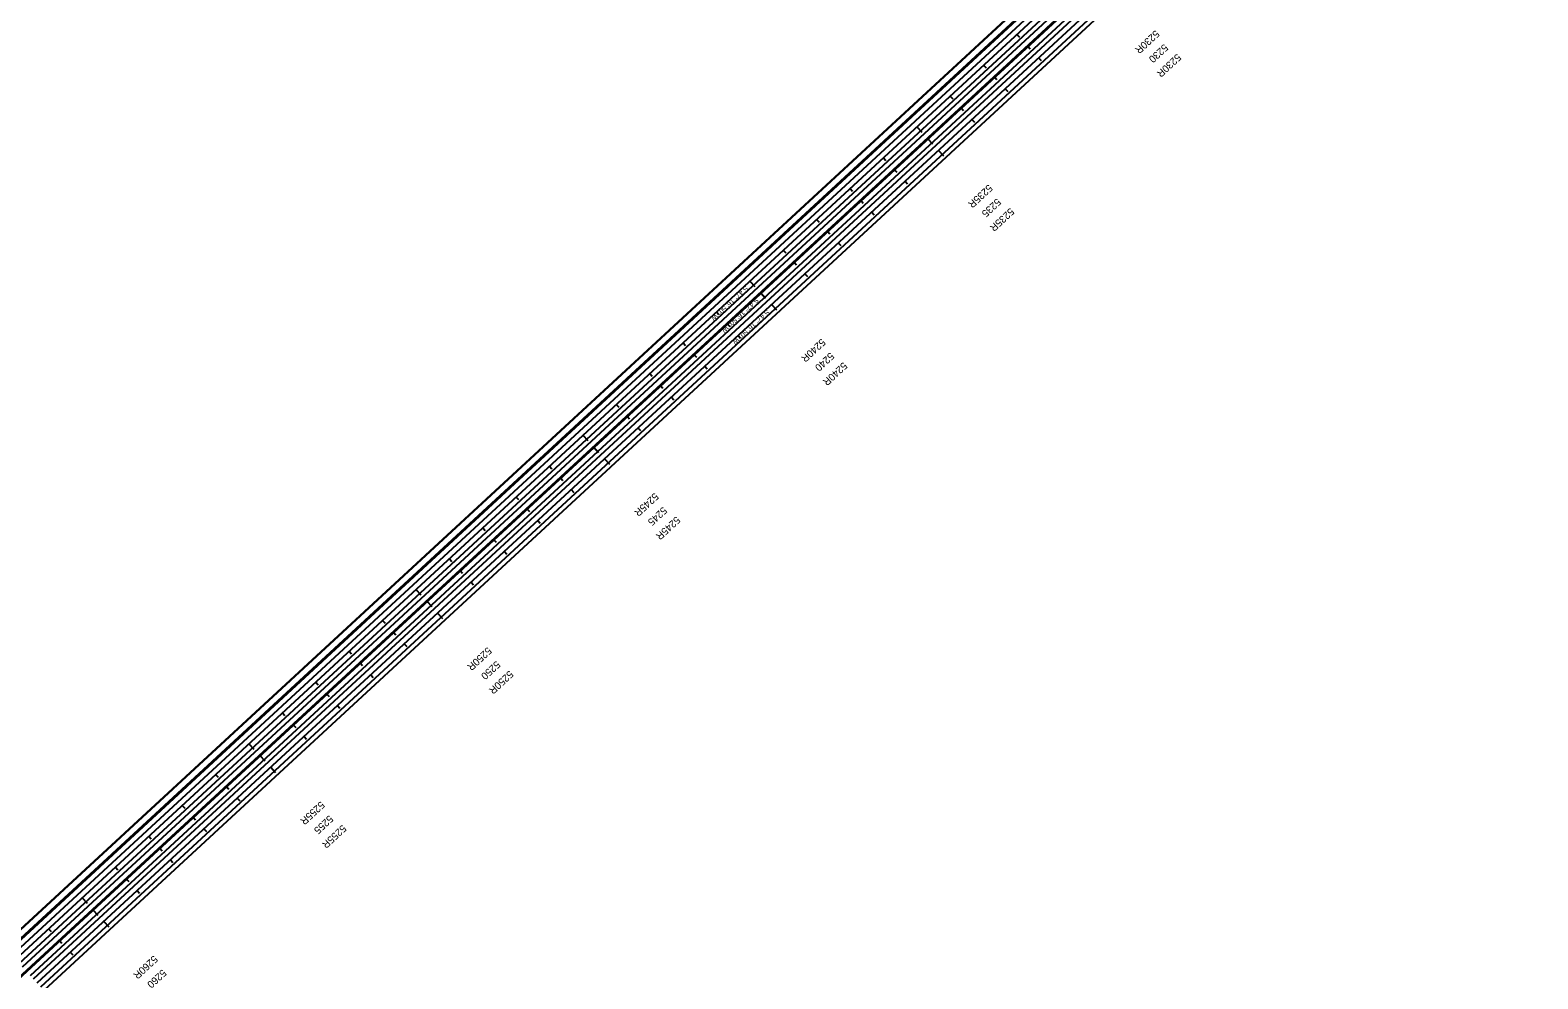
# Model space of a CAD drawing. Extents: x 2160876 to 2175625, y 601634 to 617693.
# Drawn here: x 2165605 to 2168923, y 607589 to 609675 of the extents above; entities that cross this region are included whole.
import ezdxf

# ---------------------------------------------------------------- set-up
doc = ezdxf.new("R2010")
doc.units = 0
for name, color, linetype in [('RD_HC_Cl', 7, 'Continuous'), ('RD_HC_CL_Rel', 7, 'Continuous'), ('RD_HC_Data', 7, 'Continuous'), ('RD_HC_Data_Rel', 7, 'Continuous'), ('RD_HC_Data_Tic', 7, 'Continuous'), ('RD_HC_Data_Tic_Rel', 7, 'Continuous'), ('RD_HC_TX_Rel_Sta50', 7, 'Continuous'), ('RD_HC_TX_Sta50', 7, 'Continuous'), ('RD_PD_Final_LnLine', 7, 'Continuous'), ('RD_PD_Final_TrvlWay', 7, 'Continuous'), ('RD_PD_MedBWall', 7, 'Continuous')]:
    doc.layers.add(name, color=color, linetype=linetype)

msp = doc.modelspace()

# ---------------------------------------------------------------- linework, layer by layer
at = {"layer": 'RD_HC_Cl'}
msp.add_line((2172239.9, 613739.9), (2163704.8, 605858.6), dxfattribs=at)
at = {"layer": 'RD_HC_CL_Rel'}
for p, q in [((2168658.1, 610480.3), (2165572.4, 607631)), ((2168705.8, 610428.6), (2165620.1, 607579.3))]:
    msp.add_line(p, q, dxfattribs=at)
at = {"layer": 'RD_HC_Data_Tic'}
for p, q in [((2167800.3, 609640.4), (2167805.8, 609634.5)), ((2167726.9, 609572.5), (2167732.3, 609566.7)), ((2167653.4, 609504.7), (2167658.8, 609498.8)), ((2167579.9, 609436.9), (2167590.8, 609425.1)), ((2167506.5, 609369), (2167511.9, 609363.1)), ((2167433, 609301.2), (2167438.4, 609295.3)), ((2167359.5, 609233.3), (2167365, 609227.5)), ((2167286.1, 609165.5), (2167291.5, 609159.6)), ((2167212.6, 609097.7), (2167223.4, 609085.9)), ((2167139.1, 609029.8), (2167144.6, 609023.9)), ((2167065.7, 608962), (2167071.1, 608956.1)), ((2166992.2, 608894.1), (2166997.6, 608888.3)), ((2166918.7, 608826.3), (2166924.1, 608820.4)), ((2166845.2, 608758.5), (2166856.1, 608746.7)), ((2166771.8, 608690.6), (2166777.2, 608684.7)), ((2166698.3, 608622.8), (2166703.7, 608616.9)), ((2166624.8, 608554.9), (2166630.3, 608549.1)), ((2166551.4, 608487.1), (2166556.8, 608481.2)), ((2166477.9, 608419.2), (2166488.8, 608407.5)), ((2166404.4, 608351.4), (2166409.9, 608345.5)), ((2166331, 608283.6), (2166336.4, 608277.7)), ((2166257.5, 608215.7), (2166262.9, 608209.8)), ((2166184, 608147.9), (2166189.5, 608142)), ((2166110.6, 608080), (2166121.4, 608068.3)), ((2166037.1, 608012.2), (2166042.5, 608006.3)), ((2165963.6, 607944.4), (2165969.1, 607938.5)), ((2165890.2, 607876.5), (2165895.6, 607870.6)), ((2165816.7, 607808.7), (2165822.1, 607802.8)), ((2165743.2, 607740.8), (2165754.1, 607729.1)), ((2165669.8, 607673), (2165675.2, 607667.1))]:
    msp.add_line(p, q, dxfattribs=at)
at = {"layer": 'RD_HC_Data_Tic_Rel'}
for p, q in [((2167776.5, 609666.3), (2167781.9, 609660.4)), ((2167703, 609598.4), (2167708.5, 609592.5)), ((2167824.2, 609614.6), (2167829.7, 609608.7)), ((2167629.6, 609530.6), (2167635, 609524.7)), ((2167750.8, 609546.7), (2167756.2, 609540.9)), ((2167556.1, 609462.7), (2167567, 609451)), ((2167677.3, 609478.9), (2167682.7, 609473)), ((2167482.6, 609394.9), (2167488.1, 609389)), ((2167603.8, 609411.1), (2167614.7, 609399.3)), ((2167530.4, 609343.2), (2167535.8, 609337.3)), ((2167409.2, 609327), (2167414.6, 609321.2)), ((2167456.9, 609275.4), (2167462.3, 609269.5)), ((2167335.7, 609259.2), (2167341.1, 609253.3)), ((2167383.4, 609207.5), (2167388.8, 609201.7)), ((2167262.2, 609191.4), (2167267.7, 609185.5)), ((2167310, 609139.7), (2167315.4, 609133.8)), ((2167188.8, 609123.5), (2167199.6, 609111.8)), ((2167236.5, 609071.9), (2167247.3, 609060.1)), ((2167115.3, 609055.7), (2167120.7, 609049.8)), ((2167163, 609004), (2167168.4, 608998.1)), ((2167041.8, 608987.8), (2167047.3, 608982)), ((2167089.5, 608936.2), (2167095, 608930.3)), ((2166968.4, 608920), (2166973.8, 608914.1)), ((2167016.1, 608868.3), (2167021.5, 608862.5)), ((2166894.9, 608852.2), (2166900.3, 608846.3)), ((2166942.6, 608800.5), (2166948, 608794.6)), ((2166821.4, 608784.3), (2166832.3, 608772.6)), ((2166869.1, 608732.6), (2166880, 608720.9)), ((2166748, 608716.5), (2166753.4, 608710.6)), ((2166795.7, 608664.8), (2166801.1, 608658.9)), ((2166674.5, 608648.6), (2166679.9, 608642.8)), ((2166601, 608580.8), (2166606.4, 608574.9)), ((2166722.2, 608597), (2166727.6, 608591.1)), ((2166527.6, 608513), (2166533, 608507.1)), ((2166648.7, 608529.1), (2166654.2, 608523.2)), ((2166454.1, 608445.1), (2166464.9, 608433.4)), ((2166575.3, 608461.3), (2166580.7, 608455.4)), ((2166380.6, 608377.3), (2166386, 608371.4)), ((2166501.8, 608393.4), (2166512.7, 608381.7)), ((2166307.1, 608309.4), (2166312.6, 608303.6)), ((2166428.3, 608325.6), (2166433.8, 608319.7)), ((2166233.7, 608241.6), (2166239.1, 608235.7)), ((2166354.9, 608257.8), (2166360.3, 608251.9)), ((2166160.2, 608173.8), (2166165.6, 608167.9)), ((2166281.4, 608189.9), (2166286.8, 608184)), ((2166086.7, 608105.9), (2166097.6, 608094.2)), ((2166207.9, 608122.1), (2166213.4, 608116.2)), ((2166013.3, 608038.1), (2166018.7, 608032.2)), ((2166134.5, 608054.2), (2166145.3, 608042.5)), ((2165939.8, 607970.2), (2165945.2, 607964.4)), ((2166061, 607986.4), (2166066.4, 607980.5)), ((2165866.3, 607902.4), (2165871.8, 607896.5)), ((2165987.5, 607918.6), (2165992.9, 607912.7)), ((2165914.1, 607850.7), (2165919.5, 607844.8)), ((2165792.9, 607834.5), (2165798.3, 607828.7)), ((2165840.6, 607782.9), (2165846, 607777)), ((2165719.4, 607766.7), (2165730.3, 607755)), ((2165767.1, 607715), (2165778, 607703.3)), ((2165645.9, 607698.9), (2165651.4, 607693)), ((2165693.6, 607647.2), (2165699.1, 607641.3))]:
    msp.add_line(p, q, dxfattribs=at)
at = {"layer": 'RD_PD_Final_LnLine'}
for p, q in [((2168630.1, 610510.7), (2165544.4, 607661.4)), ((2168630.7, 610509.9), (2165545.1, 607660.6)), ((2168650, 610489.1), (2165564.3, 607639.8)), ((2168658.1, 610480.3), (2165572.4, 607631)), ((2168666.2, 610471.5), (2165580.6, 607622.2)), ((2168697.7, 610437.5), (2165612, 607588.1)), ((2168705.8, 610428.6), (2165620.1, 607579.3)), ((2168714, 610419.8), (2165628.3, 607570.5))]:
    msp.add_line(p, q, dxfattribs=at)
at = {"layer": 'RD_PD_Final_TrvlWay'}
for p, q in [((2168641.8, 610497.9), (2165556.1, 607648.6)), ((2168673, 610464.1), (2165587.4, 607614.8)), ((2168690.9, 610444.8), (2165605.2, 607595.5)), ((2168720.7, 610412.5), (2165635.1, 607563.2))]:
    msp.add_line(p, q, dxfattribs=at)
at = {"layer": 'RD_PD_MedBWall'}
for p, q in [((2168640.2, 610499.7), (2165554.6, 607650.3)), ((2168641.8, 610497.9), (2165556.1, 607648.6)), ((2168454, 610245.6), (2165100.2, 607148.7)), ((2168455.6, 610243.9), (2165101.8, 607146.9))]:
    msp.add_line(p, q, dxfattribs=at)

# ---------------------------------------------------------------- texts
at = {"layer": 'RD_HC_Data'}
msp.add_text('S 47° 16\' 50" W', height=10.8, rotation=222.7195, dxfattribs=at).set_placement((2167202.1, 609087.8))
at = {"layer": 'RD_HC_Data_Rel'}
for p in [(2167179.3, 609113.6), (2167226.3, 609061.4)]:
    msp.add_text('S 47° 16\' 50" W', height=10.8, rotation=222.7195, dxfattribs=at).set_placement(p)
at = {"layer": 'RD_HC_TX_Rel_Sta50'}
for s, p in [('5230R', (2168081.1, 609676.5)), ('5230R', (2168128.8, 609624.8)), ('5235R', (2167713.8, 609337.3)), ('5235R', (2167761.5, 609285.6)), ('5240R', (2167346.4, 608998.1)), ('5240R', (2167394.2, 608946.4)), ('5245R', (2166979.1, 608658.9)), ('5245R', (2167026.8, 608607.2)), ('5250R', (2166611.8, 608319.7)), ('5250R', (2166659.5, 608268)), ('5255R', (2166244.4, 607980.5)), ('5255R', (2166292.1, 607928.8)), ('5260R', (2165877.1, 607641.3))]:
    msp.add_text(s, height=16, rotation=222.7195, dxfattribs=at).set_placement(p)
at = {"layer": 'RD_HC_TX_Sta50'}
for s, p in [('5230', (2168100.1, 609646.2)), ('5235', (2167732.4, 609306.6)), ('5240', (2167365.4, 608967.7)), ('5245', (2166997.7, 608628.2)), ('5250', (2166630.8, 608289.3)), ('5255', (2166263.1, 607949.8)), ('5260', (2165896.1, 607610.9))]:
    msp.add_text(s, height=16, rotation=222.7195, dxfattribs=at).set_placement(p)

doc.saveas('drawing.dxf')
